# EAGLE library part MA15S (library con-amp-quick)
AMP QUICK CONNECTOR
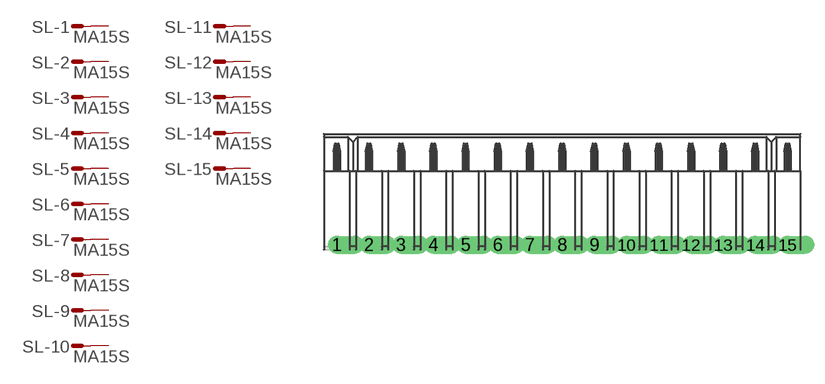
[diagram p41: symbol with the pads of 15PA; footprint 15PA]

Designator prefix SL; gates -1=M -2=M -3=M -4=M -5=M -6=M -7=M -8=M -9=M -10=M -11=M -12=M -13=M -14=M -15=M

## MA15S  [15PA]
1  -1:S  pas
2  -2:S  pas
3  -3:S  pas
4  -4:S  pas
5  -5:S  pas
6  -6:S  pas
7  -7:S  pas
8  -8:S  pas
9  -9:S  pas
10  -10:S  pas
11  -11:S  pas
12  -12:S  pas
13  -13:S  pas
14  -14:S  pas
15  -15:S  pas

## Footprint 15PA (pad centres in mm)
AMP QUICK CONNECTOR
drill 0.914 offset: 1 -17.78,0; 2 -15.24,0; 3 -12.7,0; 4 -10.16,0; 5 -7.62,0; 6 -5.08,0; 7 -2.54,0; 8 0,0; 9 2.54,0; 10 5.08,0; 11 7.62,0; 12 10.16,0; 13 12.7,0; 14 15.24,0; 15 17.78,0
